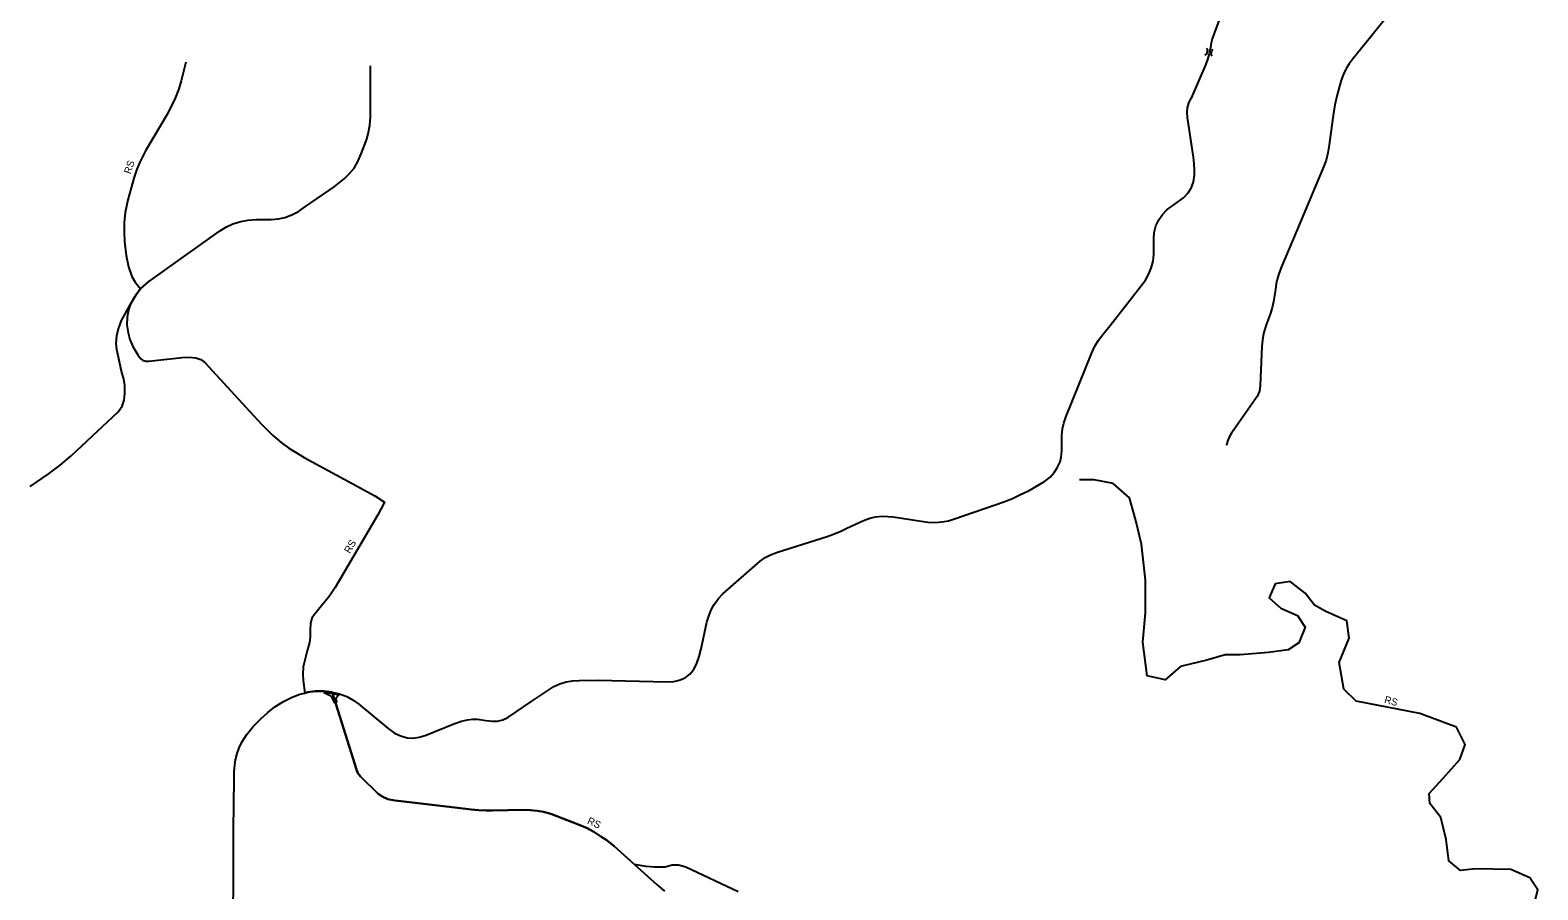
# Model space of a CAD drawing. Extents: x -546703 to -534152, y -1046534 to -1035676.
# Drawn here: x -546385 to -544284, y -1044501 to -1043304 of the extents above; entities that cross this region are included whole.
import ezdxf

# ---------------------------------------------------------------- set-up
doc = ezdxf.new("R2010")
doc.units = 0
for name, color, linetype in [('Vrstva 11', 7, 'Continuous'), ('Vrstva 22', 7, 'Continuous'), ('Vrstva 8', 7, 'Continuous')]:
    doc.layers.add(name, color=color, linetype=linetype)

msp = doc.modelspace()

# ---------------------------------------------------------------- linework, layer by layer
at = {"layer": 'Vrstva 11'}
for points in [[(-544728.5, -1043289.3), (-544738.1, -1043315.8), (-544739.6, -1043321), (-544740.6, -1043327.6), (-544742.4, -1043336.5), (-544744.3, -1043343.2), (-544747.2, -1043350.9), (-544767.4, -1043398.1)], [(-544496.2, -1043287), (-544525.3, -1043323.2), (-544541.7, -1043343.2), (-544547.2, -1043350.3), (-544551.5, -1043357.2), (-544555.4, -1043364.8), (-544558.4, -1043373.4), (-544560.9, -1043381.7), (-544564.1, -1043393.7), (-544567.1, -1043407.4), (-544569.7, -1043422.4), (-544571.6, -1043435.8), (-544575, -1043463.4), (-544576.9, -1043474.6), (-544579.4, -1043484.6), (-544582.5, -1043493), (-544620, -1043582.6), (-544642.1, -1043634.4), (-544645.9, -1043644.6), (-544647.8, -1043651.1), (-544648.8, -1043656.7), (-544650, -1043664.9), (-544652.5, -1043681.5), (-544654.5, -1043690.4), (-544657.4, -1043699.3), (-544662.8, -1043714), (-544664.9, -1043720), (-544666.5, -1043726), (-544667.9, -1043735.3), (-544668.9, -1043744), (-544670.6, -1043776.8), (-544671.1, -1043798.8), (-544672.3, -1043806.4), (-544675.5, -1043814.2), (-544711.3, -1043864.9), (-544714.5, -1043870.8), (-544716.7, -1043876.1), (-544718, -1043882.1)], [(-546385.2, -1043939.5), (-546360, -1043922.3), (-546343.5, -1043909.5), (-546328.2, -1043896.6), (-546262.7, -1043835.3), (-546257.1, -1043827.3), (-546254.3, -1043819.3), (-546253.1, -1043809.8), (-546253.1, -1043798.5), (-546254.7, -1043790), (-546258, -1043778.5), (-546264.6, -1043748.3), (-546265.3, -1043740.3), (-546264.6, -1043729.7), (-546262.5, -1043721), (-546257.8, -1043708), (-546246, -1043686.3), (-546237.1, -1043671.3), (-546231.4, -1043664.2), (-546220.3, -1043654.3), (-546201, -1043640.4), (-546121.4, -1043583.8), (-546111.5, -1043577.4), (-546102.6, -1043573.4), (-546091.7, -1043570.1), (-546081.8, -1043568.3), (-546070.5, -1043567.6), (-546049.3, -1043567.6), (-546039.4, -1043566.6), (-546030.3, -1043564.7), (-546020.4, -1043561), (-546011.4, -1043556), (-546001.5, -1043549.4), (-545961.7, -1043521.8), (-545947.8, -1043510.8), (-545940.5, -1043503.9), (-545933.9, -1043495.9), (-545928, -1043485.8), (-545924, -1043476.1), (-545916.3, -1043455.6), (-545913.9, -1043445.9), (-545912, -1043436), (-545910.8, -1043425), (-545910.8, -1043353.1)], [(-546102.5, -1044544.8), (-546102, -1044477.9), (-546101.8, -1044417.5), (-546101, -1044347.3), (-546100.8, -1044336.9), (-546100.1, -1044327.4), (-546099.2, -1044320.3), (-546096.9, -1044311.5), (-546094, -1044303.3), (-546090.1, -1044295.5), (-546083.8, -1044285.6), (-546074.3, -1044273.9), (-546064, -1044263), (-546054.1, -1044254.1), (-546044.5, -1044246.3), (-546032.2, -1044239), (-546020.1, -1044232.8), (-546009.4, -1044228.8), (-546002.5, -1044227.2), (-545998.5, -1044226.2), (-545987.9, -1044224.7), (-545975.8, -1044224.5), (-545964.2, -1044225.9), (-545954.3, -1044228.1), (-545944, -1044231.9), (-545934.9, -1044237.1), (-545927.2, -1044242.7), (-545886.4, -1044276.6), (-545877.6, -1044283), (-545868, -1044287.4), (-545859.5, -1044289.8), (-545852.2, -1044290.1), (-545843.2, -1044288.8), (-545835, -1044286.3), (-545795, -1044270), (-545784.1, -1044266.3), (-545775.7, -1044264.5), (-545768.9, -1044263.8), (-545761.9, -1044263.7), (-545750.1, -1044265.3), (-545741.2, -1044266.5), (-545733.9, -1044266.2), (-545726.5, -1044264.5), (-545719.4, -1044261.2), (-545686.1, -1044238.6), (-545655.4, -1044218.3), (-545647.1, -1044214.2), (-545638.4, -1044211.6), (-545629.7, -1044210), (-545620.3, -1044209.5), (-545593.9, -1044209.4), (-545498, -1044211.7), (-545488.2, -1044210.9), (-545481, -1044209.2), (-545472.7, -1044205.9), (-545465.8, -1044200.9), (-545460.7, -1044194.9), (-545456.9, -1044186.9), (-545453, -1044176.5), (-545450.3, -1044165.4), (-545442.1, -1044128.4), (-545439.3, -1044118.6), (-545436, -1044110.2), (-545432.3, -1044103.8), (-545426.1, -1044095.5), (-545419.9, -1044088.9), (-545367.9, -1044043.4), (-545361, -1044038.4), (-545353.8, -1044034.6), (-545343.9, -1044031), (-545274.6, -1044009.2), (-545265.7, -1044005.9), (-545255.8, -1044001.5), (-545246.2, -1043996.9), (-545224.9, -1043987.1), (-545215.2, -1043983.6), (-545207.2, -1043981.8), (-545198.1, -1043980.9), (-545190.1, -1043981.1), (-545182.5, -1043981.8), (-545143.9, -1043987.9), (-545134.3, -1043989.1), (-545124.3, -1043989.5), (-545114.8, -1043988.8), (-545105.7, -1043987.1), (-545097.1, -1043984.5), (-545026.9, -1043960.1), (-545015.7, -1043955.7), (-545006, -1043951.2), (-544993.4, -1043944.8), (-544972, -1043932.5), (-544964.1, -1043926.3), (-544958.2, -1043919.9), (-544954, -1043913.4), (-544950.2, -1043905.2), (-544948.6, -1043898.5), (-544947.8, -1043889.1), (-544947.5, -1043868.3), (-544946.6, -1043859.2), (-544944.8, -1043851.1), (-544942.1, -1043843), (-544906, -1043753), (-544901.6, -1043744), (-544896.5, -1043735.3), (-544890.6, -1043727.6), (-544880.4, -1043715), (-544831.3, -1043652), (-544827, -1043644.2), (-544823, -1043635), (-544820.4, -1043625.3), (-544819.4, -1043616), (-544819.3, -1043607.3), (-544819.5, -1043594.1), (-544818.9, -1043585.4), (-544816.6, -1043576.3), (-544812.5, -1043567.8), (-544807.4, -1043560.4), (-544801.2, -1043554.1), (-544778.1, -1043537.1), (-544771.4, -1043530.4), (-544766.9, -1043522.6), (-544764.3, -1043514.8), (-544763, -1043505.8), (-544762.7, -1043498.6), (-544763.2, -1043489.8), (-544764, -1043480.4), (-544772.5, -1043425.1), (-544773, -1043418), (-544772.6, -1043411.8), (-544770.6, -1043405.3), (-544767.4, -1043398.1)], [(-545964.2, -1044225.9), (-545937.8, -1044310.1), (-545930.6, -1044333.6), (-545928.4, -1044338.9), (-545924.7, -1044343.4), (-545900.3, -1044367.8), (-545893.9, -1044372), (-545887, -1044374.9), (-545877.3, -1044377.1), (-545868.9, -1044377.9), (-545793.5, -1044386.6), (-545770.8, -1044389.3), (-545760.7, -1044390.5), (-545750, -1044390.9), (-545740.3, -1044390.7), (-545698.7, -1044389.7), (-545688.6, -1044390.2), (-545678.7, -1044391.2), (-545669.9, -1044392.8), (-545659.5, -1044395.7), (-545620, -1044410.6), (-545609.2, -1044415.5), (-545599.9, -1044420.8), (-545590, -1044426.9), (-545581.3, -1044432.5), (-545571.4, -1044440.7), (-545543.1, -1044466), (-545511.3, -1044494.4), (-545501.1, -1044503.4)]]:
    msp.add_lwpolyline(points, dxfattribs=at)
msp.add_lwpolyline([(-545975.9, -1044226.5), (-545971.9, -1044228.1), (-545968.2, -1044230), (-545965.8, -1044232), (-545963.7, -1044235.1), (-545961.6, -1044240.2), (-545958.1, -1044239.5), (-545958.8, -1044235.9), (-545958.3, -1044233.4), (-545957.1, -1044231.6), (-545954.9, -1044230), (-545964.5, -1044227.8)], close=True, dxfattribs=at)
at = {"layer": 'Vrstva 22'}
for points in [[(-546168.1, -1043348.1), (-546174.6, -1043374.3), (-546177.9, -1043385.4), (-546183.1, -1043398.3), (-546193.7, -1043420), (-546224.3, -1043471.6), (-546232.4, -1043487.7), (-546236.6, -1043497.3), (-546240.8, -1043509.8), (-546244.6, -1043523.2), (-546249.3, -1043540), (-546252.6, -1043557.7), (-546254.3, -1043572), (-546254.3, -1043584.8), (-546253.8, -1043598.2), (-546251.4, -1043617.5), (-546248.1, -1043633.5), (-546243.4, -1043646.7), (-546238.7, -1043654.5), (-546231.4, -1043664.2), (-546237.1, -1043671.3), (-546241.5, -1043678.3), (-546246, -1043686.3), (-546248.4, -1043693.4), (-546250, -1043703.5), (-546250.5, -1043714.1), (-546248.8, -1043725.5), (-546246.5, -1043734.7), (-546242.2, -1043744.3), (-546235.2, -1043756.1), (-546231.6, -1043761), (-546228.8, -1043763.2), (-546224.1, -1043764.6), (-546219.9, -1043764.6), (-546173.5, -1043759.6), (-546163.6, -1043759.4), (-546154.4, -1043760.1), (-546147.6, -1043762.5), (-546141.9, -1043766.5), (-546079.5, -1043834.6), (-546062.5, -1043853.2), (-546047.5, -1043867.8), (-546035.4, -1043878.2), (-546024.6, -1043886.2), (-546015.7, -1043891.6), (-546003.2, -1043898.9), (-545936.5, -1043935), (-545905, -1043952.4), (-545891.5, -1043961.4), (-545900.7, -1043979.1), (-545960.3, -1044080.2), (-545968.8, -1044092.7), (-545979.4, -1044105.9), (-545989.7, -1044118.1), (-545992.6, -1044122.8), (-545994.5, -1044130.8), (-545994.9, -1044138.8), (-545995.2, -1044149.2), (-545996.1, -1044156.8), (-545999.4, -1044168.3), (-546004.6, -1044190.7), (-546005.3, -1044201.5), (-546004.6, -1044209.8), (-546002.5, -1044227.2)], [(-544290.8, -1044526.7), (-544284.4, -1044501.3), (-544295.7, -1044484.7), (-544321.9, -1044473), (-544371.1, -1044472.2), (-544392.1, -1044474.6), (-544408.2, -1044460.9), (-544412.2, -1044431.1), (-544419.5, -1044400.4), (-544434.8, -1044381.1), (-544435.6, -1044367.3), (-544416.3, -1044345.6), (-544392.9, -1044319.8), (-544385.6, -1044298.8), (-544397.7, -1044274.6), (-544448.9, -1044255.6), (-544537.7, -1044238.7), (-544554.6, -1044221.7), (-544561.1, -1044184.6), (-544547.4, -1044150.7), (-544550.6, -1044126.5), (-544579.6, -1044113.6), (-544595.8, -1044104.8), (-544608.7, -1044087.8), (-544629.7, -1044071.7), (-544650.6, -1044074.9), (-544658.7, -1044094.3), (-544642.6, -1044108.8), (-544619.2, -1044119.3), (-544608.7, -1044135.4), (-544617.6, -1044157.2), (-544632.1, -1044166.9), (-544659.5, -1044170.9), (-544699, -1044174.1), (-544720, -1044174.1), (-544745.8, -1044181.4), (-544782.1, -1044190.3), (-544803.9, -1044208.8), (-544828.9, -1044203.2), (-544834.6, -1044156.4), (-544831.3, -1044115.2), (-544831.3, -1044070.1), (-544836.6, -1044019.7), (-544844.6, -1043986.6), (-544853.5, -1043955.1), (-544876.1, -1043935), (-544902.7, -1043930.1), (-544922.9, -1043930.1)], [(-545398.7, -1044504.2), (-545471.7, -1044469.9), (-545481.7, -1044467.1), (-545490.6, -1044467.1), (-545500.6, -1044469.6), (-545515.3, -1044469.9), (-545526.8, -1044469), (-545543.1, -1044466), (-545571.4, -1044440.7), (-545581.3, -1044432.5), (-545590, -1044426.9), (-545599.9, -1044420.8), (-545609.2, -1044415.5), (-545620, -1044410.6), (-545659.5, -1044395.7), (-545669.9, -1044392.8), (-545678.7, -1044391.2), (-545688.6, -1044390.2), (-545698.7, -1044389.7), (-545740.3, -1044390.7), (-545750, -1044390.9), (-545760.7, -1044390.5), (-545770.8, -1044389.3), (-545793.5, -1044386.6), (-545868.9, -1044377.9), (-545877.3, -1044377.1), (-545887, -1044374.9), (-545893.9, -1044372), (-545900.3, -1044367.8), (-545924.7, -1044343.4), (-545928.4, -1044338.9), (-545930.6, -1044333.6), (-545937.8, -1044310.1), (-545964.2, -1044225.9), (-545975.8, -1044224.5), (-545987.9, -1044224.7), (-545998.5, -1044226.2), (-546002.5, -1044227.2)]]:
    msp.add_lwpolyline(points, dxfattribs=at)
at = {"layer": 'Vrstva 8'}
for points in [[(-544748.5, -1043338.1), (-544745.6, -1043336.7), (-544744.4, -1043331.4), (-544745.7, -1043328.8)], [(-544738.1, -1043339.7), (-544739.5, -1043337), (-544738.6, -1043332.1), (-544736.7, -1043330.5)]]:
    msp.add_lwpolyline(points, dxfattribs=at)

# ---------------------------------------------------------------- texts
at = {"layer": 'Vrstva 22'}
for rotation, p in [(71.2519, (-546245.4, -1043504.7)), (59.4855, (-545939.8, -1044033.5)), (344.72, (-544499.1, -1044240.6)), (335.7013, (-545609.8, -1044408.7))]:
    msp.add_text('RS', height=10, rotation=rotation, dxfattribs=at).set_placement(p)

doc.saveas('drawing.dxf')
